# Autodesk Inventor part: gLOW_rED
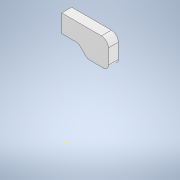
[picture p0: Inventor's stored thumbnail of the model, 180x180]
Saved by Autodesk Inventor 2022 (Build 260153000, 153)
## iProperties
Created: 2022-02
Part Number: gLOW_rED
Material: ABS Plastic
Document SubType Name: Modeling
Designer: joshw
Density: 1.06 g/cm^3
Appearance: Smooth - White
Author: joshw
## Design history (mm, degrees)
sketch "Sketch1"
  geometry: L1 (28.06, 14.711)-(28.06, 12.425); L2 (28.06, 12.425)-(29.946, 12.425); L3 (30.395, 12.239)-(31.166, 11.468); L4 (31.615, 11.282)-(33.394, 11.282); L5 (34.029, 11.917)-(34.029, 13.822); L6 (33.14, 14.711)-(28.06, 14.711); A1 r 0.889 centre (33.14, 13.822) between (34.029, 13.822) and (33.14, 14.711); A2 r 0.635 centre (33.394, 11.917) between (33.394, 11.282) and (34.029, 11.917); A3 r 0.635 centre (31.615, 11.917) between (31.166, 11.468) and (31.615, 11.282); A4 r 0.635 centre (29.946, 11.79) between (30.395, 12.239) and (29.946, 12.425); 1 further point
  constraints: 12 end point, 8 point on circle, 8 tangent, 4 centre point, 3 perpendicular, 2 equal radius, 1 horizontal, 1 parallel
  dimensions: "d0" = 135 deg angle of L3 L4; "d1" = 0.889 radius of A1; "d2" = 0.635 radius of A2; "d5" = 5.08 distance of L6.start L1.start; "d6" = 2.286 distance of L1.start L1.end; "d7" = 1.88595 distance of L1.end L2.end; "d8" = 1.905 distance of L5.start L5.end
extrude "Extrusion1" new body sketch "Sketch1" stored distance "d3" = 1.27; taper "d4" = 0 deg
sketch "Sketch2"
  geometry: 1 further point
sketch "Sketch3"
  geometry: L1 (-1.016, 1.778)-(-0.762, 1.778); L2 (-0.762, 1.778)-(-0.762, 0.508); L3 (-0.762, 0.508)-(-1.016, 0.508); L4 (-1.016, 0.508)-(-1.016, 1.778); L5 (-1.016, 1.778)-(-0.762, 0.508); L6 (-0.762, 1.778)-(-1.016, 0.508); L7 (-0.635, 2.402)-(-0.635, -0.451) reference; L8 (-1.27, -0.186)-(0, -0.186) reference; L9 (0, 2.286)-(0, 0) reference; L10 (0, 1.143)-(-1.431, 1.143); L11 (-0.254, 1.778)-(-0.508, 1.778); L12 (-0.508, 1.778)-(-0.508, 0.508); L13 (-0.508, 0.508)-(-0.254, 0.508); L14 (-0.254, 0.508)-(-0.254, 1.778); L15 (-0.254, 1.778)-(-0.508, 0.508); L16 (-0.508, 1.778)-(-0.254, 0.508); 5 further points
  constraints: 28 end point, 6 midpoint, 6 symmetric about line, 2 horizontal, 2 parallel, 2 perpendicular, 1 point on line, 1 vertical
  dimensions: "d9" = 0.254 distance of L2.end L3.end; "d10" = 0.254 diameter of L2 L7; "d11" = 1.27 distance between parallel lines of L3 L1
extrude "Extrusion2" cut sketch "Sketch3" distance "d12" = 4.445; taper "d13" = 0 deg
body "Solid1"
